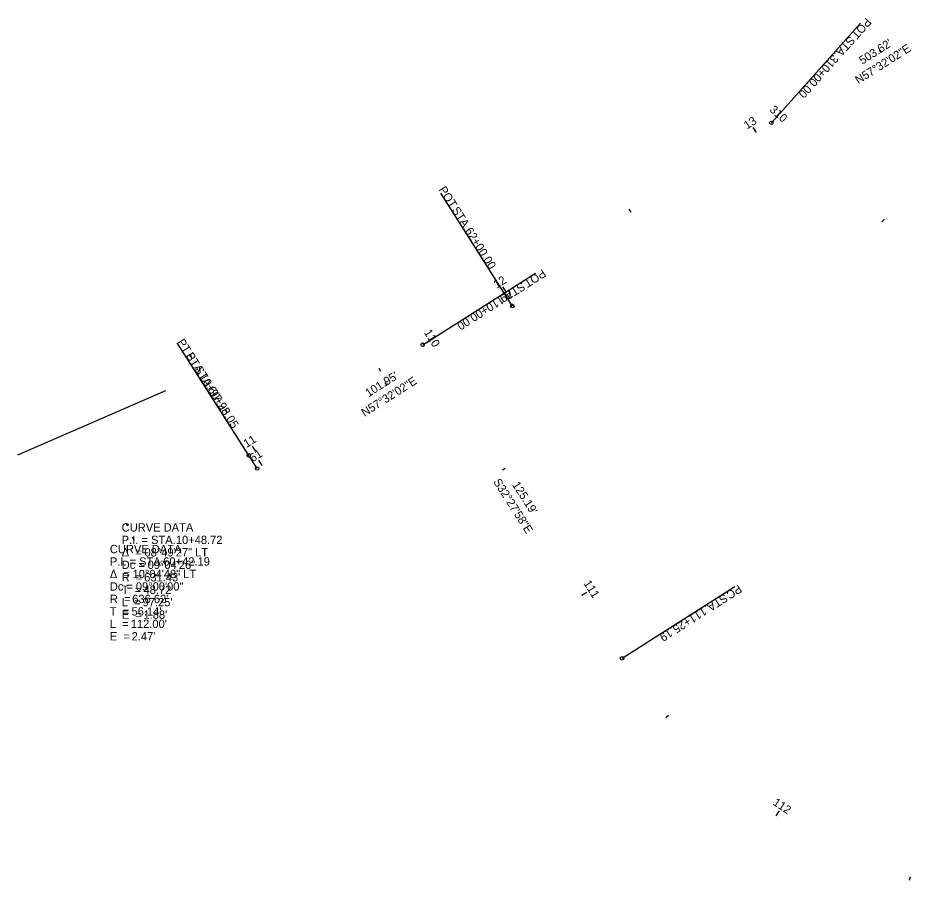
# Model space of a CAD drawing. Extents: x 143421 to 147121, y 511505 to 514560.
# Drawn here: x 144835.3 to 145136.4, y 512822.4 to 513112.9 of the extents above; entities that cross this region are included whole.
import ezdxf

# ---------------------------------------------------------------- set-up
doc = ezdxf.new("R2010")
doc.units = 0
for name, color, linetype in [('CM_Corridor_Conceptual', 7, 'Continuous'), ('CM_Corridor_Range_Conceptual', 7, 'Continuous'), ('CM_Corridor_Top_Mesh', 7, 'Continuous'), ('DR_P_Sediment_Basin', 7, 'Continuous'), ('DT_P_Tie', 7, 'Continuous'), ('DT_X_Triangles', 7, 'Continuous'), ('DT_X_Void', 7, 'Continuous'), ('MD_P_Surface_Finished_Grade', 7, 'Continuous'), ('PF_X_Ground_Line', 7, 'Continuous'), ('SC_Scratch1', 7, 'Continuous'), ('SC_Scratch2', 7, 'Continuous')]:
    doc.layers.add(name, color=color, linetype=linetype)

msp = doc.modelspace()

# ---------------------------------------------------------------- linework, layer by layer
at = {"layer": 'CM_Corridor_Conceptual'}
for p, q in [((145002.01, 513015.81), (145000.94, 513017.5)), ((144959.83, 512988.97), (144959.18, 512989.99)), ((144917.64, 512962.13), (144916.57, 512963.82)), ((144874.52, 512936.85), (144873.96, 512937.9))]:
    msp.add_line(p, q, dxfattribs=at)
at = {"layer": 'DT_P_Tie'}
for p, q in [((145089.33, 513077.52), (145119.32, 513111.07)), ((144971.8, 513002.75), (145009.77, 513026.9)), ((144913.21, 512965.47), (144889.05, 513003.43)), ((145039.01, 512897.12), (145076.97, 512921.28))]:
    msp.add_line(p, q, dxfattribs=at)
for centre in [(145089.33, 513077.52), (144971.8, 513002.75), (144913.21, 512965.47), (145039.01, 512897.12)]:
    msp.add_circle(centre, 0.6, dxfattribs=at)
at = {"layer": 'DT_X_Triangles'}
for p, q in [((145126.46, 513101.14), (145125.81, 513102.16)), ((145089.33, 513077.52), (145090.66, 513079.01)), ((145084.27, 513074.3), (145083.2, 513075.99)), ((145042.09, 513047.46), (145041.44, 513048.48)), ((145126.61, 513044.2), (145127.41, 513045.09)), ((144999.9, 513020.62), (144998.83, 513022.31)), ((144971.8, 513002.75), (144973.49, 513003.82)), ((144957.71, 512993.78), (144957.07, 512994.8)), ((144915.53, 512966.94), (144914.46, 512968.63)), ((144998.64, 512960.56), (144999.65, 512961.2)), ((144872.43, 512941.62), (144871.87, 512942.68)), ((145025.48, 512918.38), (145027.17, 512919.45)), ((145053.72, 512877.17), (145054.63, 512877.95)), ((145090.94, 512844.03), (145092.05, 512845.69)), ((145135.83, 512822.37), (145136.19, 512823.51))]:
    msp.add_line(p, q, dxfattribs=at)
at = {"layer": 'DT_X_Void'}
msp.add_line((144835.34, 512965.68), (144885.18, 512987.29), dxfattribs=at)
at = {"layer": 'SC_Scratch2'}
for p, q in [((145002.01, 513015.81), (144977.86, 513053.78)), ((144915.99, 512961.08), (144891.84, 512999.05))]:
    msp.add_line(p, q, dxfattribs=at)
for centre in [(145002.01, 513015.81), (144915.99, 512961.08)]:
    msp.add_circle(centre, 0.6, dxfattribs=at)

# ---------------------------------------------------------------- texts
at = {"layer": 'CM_Corridor_Conceptual'}
for s, p in [('62', (144998.9, 513016.8)), ('61', (144914.52, 512963.11))]:
    msp.add_text(s, height=2.8, rotation=32.4662, dxfattribs=at).set_placement(p)
at = {"layer": 'CM_Corridor_Range_Conceptual'}
msp.add_text("101.95'", height=2.8, rotation=32.4662, dxfattribs=at).set_placement((144953.55, 512985.02))
at = {"layer": 'CM_Corridor_Top_Mesh'}
for s, rotation, p in [("503.62'", 32.4662, (145120, 513097.09)), ("125.19'", 302.4662, (145001.85, 512955.59))]:
    msp.add_text(s, height=2.8, rotation=rotation, dxfattribs=at).set_placement(p)
at = {"layer": 'DR_P_Sediment_Basin'}
for s, p in [('CURVE DATA', (144866.35, 512932.52)), ('P.I. = STA. ', (144866.35, 512928.32)), ('60+42.19', (144884.34, 512928.32)), ('Δ  = ', (144866.35, 512924.12)), ('10°04\'48" LT', (144874, 512924.12)), ('Dc = ', (144866.35, 512919.92)), ('09°00\'00"', (144875.1, 512919.92)), ('R  = ', (144866.35, 512915.72)), ("636.62'", (144873.89, 512915.72)), ('T  = ', (144866.35, 512911.52)), ("56.14'", (144873.67, 512911.52)), ('L  = ', (144866.35, 512907.32)), ("112.00'", (144873.39, 512907.32)), ('E  = ', (144866.35, 512903.12)), ("2.47'", (144873.69, 512903.12))]:
    msp.add_text(s, height=2.8, dxfattribs=at).set_placement(p)
at = {"layer": 'DT_P_Tie'}
for s, rotation, p in [('POT', 228.2018, (145121.22, 513113.13)), (' STA. ', 228.2018, (145116.42, 513107.76)), ('310+00.00', 228.2018, (145110.12, 513100.72)), ('POT', 212.4662, (145012.15, 513028.37)), (' STA. ', 212.4662, (145006.08, 513024.5)), ('110+00.00', 212.4662, (144998.1, 513019.43)), ('PT', 302.4662, (144888.95, 513003.66)), (' STA. ', 302.4662, (144891.32, 512999.94)), ('10+97.25', 302.4662, (144896.4, 512991.96)), ('PC', 212.4662, (145078.23, 512922.03)), (' STA. ', 212.4662, (145074.36, 512919.56)), ('111+25.19', 212.4662, (145066.39, 512914.49))]:
    msp.add_text(s, height=2.8, rotation=rotation, dxfattribs=at).set_placement(p)
at = {"layer": 'DT_X_Triangles'}
for s, rotation, p in [('310', 318.2018, (145088.5, 513081.62)), ('13', 32.4662, (145081.11, 513075.26)), ('12', 32.4662, (144996.73, 513021.57)), ('110', 302.4662, (144972.11, 513006.91)), ('11', 32.4662, (144912.47, 512967.96)), ('111', 302.4662, (145025.9, 512922.38)), ('112', 326.2777, (145089.6, 512847.93))]:
    msp.add_text(s, height=2.8, rotation=rotation, dxfattribs=at).set_placement(p)
at = {"layer": 'MD_P_Surface_Finished_Grade'}
for s, p in [('CURVE DATA', (144870.34, 512939.82)), ('P.I. = STA. ', (144870.34, 512935.62)), ('10+48.72', (144888.6, 512935.62)), ('Δ  = ', (144870.34, 512931.42)), ('08°49\'27" LT', (144878.01, 512931.42)), ('Dc = ', (144870.34, 512927.22)), ('09°04\'26"', (144879.08, 512927.22)), ('R  = ', (144870.34, 512923.02)), ("631.43'", (144877.92, 512923.02)), ('T  = ', (144870.34, 512918.82)), ("48.72'", (144877.68, 512918.82)), ('L  = ', (144870.34, 512914.62)), ("97.25'", (144877.38, 512914.62)), ('E  = ', (144870.34, 512910.42)), ("1.88'", (144877.68, 512910.42))]:
    msp.add_text(s, height=2.8, dxfattribs=at).set_placement(p)
at = {"layer": 'PF_X_Ground_Line'}
for s, rotation, p in [('N57°32\'02"E', 32.4662, (145118.65, 513090.49)), ('S32°27\'58"E', 302.4662, (144995.48, 512956.58))]:
    msp.add_text(s, height=2.8, rotation=rotation, dxfattribs=at).set_placement(p)
at = {"layer": 'SC_Scratch1'}
msp.add_text('N57°32\'02"E', height=2.8, rotation=32.4662, dxfattribs=at).set_placement((144952.2, 512978.43))
at = {"layer": 'SC_Scratch2'}
for s, p in [('POT', (144977.09, 513055.05)), (' STA. ', (144980.92, 513049.04)), ('62+00.00', (144985.92, 513041.17)), ('PT', (144891.85, 512999.1)), (' STA. ', (144894.19, 512995.43)), ('60+98.05', (144899.19, 512987.56))]:
    msp.add_text(s, height=2.8, rotation=302.4662, dxfattribs=at).set_placement(p)

doc.saveas('drawing.dxf')
